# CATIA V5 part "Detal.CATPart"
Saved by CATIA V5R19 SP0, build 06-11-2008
Part number: Detal
Bounding box of the stored display mesh (mm): x -52.829 to 97.171, y -21.934 to 128.066, z 0 to 80
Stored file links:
  E:\Podręcznik\catia\symulacja\Z modelem obrabiarki\Detal\Detal.CATPart
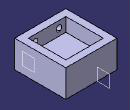
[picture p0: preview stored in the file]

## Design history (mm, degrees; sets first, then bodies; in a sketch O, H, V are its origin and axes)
Body1 "Detal" (main body)
  Sketch1 on xy-plane, origin (0, 0, 0), H (1, 0, 0), V (0, 1, 0)
    line L1 (-52.8293, 128.0659) -> (97.1707, 128.0659)
    line L2 (97.1707, 128.0659) -> (97.1707, -21.9341)
    line L3 (97.1707, -21.9341) -> (-52.8293, -21.9341)
    line L4 (-52.8293, -21.9341) -> (-52.8293, 128.0659)
    point P3 (97.1707, -21.9341)
    distance P3 L1 = 150
    length L3 = 150
    horizontal: L1 H, L3 H
    vertical: L2 V, L4 V
  Pad1: profile Sketch1, direction (0, 0, 1), length 80
  Sketch2 on end face of Pad1, origin (0, 0, 80), H (1, 0, 0), V (0, 1, 0)
    line L1 (-32.8293, 108.0659) -> (77.1707, 108.0659)
    line L2 (77.1707, 108.0659) -> (77.1707, -1.9341)
    line L3 (77.1707, -1.9341) -> (-32.8293, -1.9341)
    line L4 (-32.8293, -1.9341) -> (-32.8293, 108.0659)
    reference projected line E1 (97.1707, 128.0659) -> (-52.8293, 128.0659) from edge [face of Pad1 from Sketch1.L1 | end face of Pad1]
    reference projected line E2 (97.1707, -21.9341) -> (97.1707, 128.0659) from edge [face of Pad1 from Sketch1.L2 | end face of Pad1]
    reference projected line E3 (-52.8293, -21.9341) -> (97.1707, -21.9341) from edge [face of Pad1 from Sketch1.L3 | end face of Pad1]
    length L1 = 110
    distance L2 E2 = 20
    distance L3 E3 = 20
    length L2 = 110
    horizontal: L1 H, L3 H, E1 H
    vertical: L2 V, L4 V
  Pocket1: profile Sketch2, direction (0, 0, -1), length 40
  Plane1: type Offset, Offset 40, RefPlane face of Pad1 from Sketch1.L2
  Sketch3 on Plane1, origin (57.1707, 0, 0), H (0, -1, 0), V (0, 0, 1)
    axis line L1 (-59.4952, 83.3318) -> (64.7362, 37.931)
    line L2 (-52.1356, 89.1597) -> (64.7008, 46.4614)
    line L3 (64.7008, 46.4614) -> (61.9548, 38.9475)
    point P5 (61.9548, 38.9475)
    line L4 (-52.1356, 89.1597) -> (-54.8816, 81.6458)
    point P6 (-54.8816, 81.6458)
    distance L1 L2 = 8
    perpendicularity: L3 L1, L4 L1
    coincidence: P5 L1, P6 L1
  Groove1: profile Sketch3, axis Sketch3.L1, angle 360
  Plane2: type Offset, Offset 40, RefPlane face of Pad1 from Sketch1.L4
  Sketch4 on Plane2, origin (-12.8293, 0, 0), H (0, 1, 0), V (0, 0, 1)
    axis line L1 (-75.2929, 31.0546) -> (52.1237, 81.2631)
    line L2 (-45.5258, 51.3831) -> (28.5005, 80.5531)
    line L3 (28.5005, 80.5531) -> (31.4334, 73.1101)
    point P1 (31.4334, 73.1101)
    line L4 (-45.5258, 51.3831) -> (-42.5929, 43.9401)
    point P2 (-42.5929, 43.9401)
    distance L1 L2 = 8
    perpendicularity: L3 L1, L4 L1
    coincidence: P1 L1, P2 L1
  Groove2: profile Sketch4, axis Sketch4.L1, angle 360
Body2 "Polfabrykat"
  Sketch5 on start face of Pad1, origin (0, 0, 0), H (1, 0, 0), V (0, -1, 0)
    point P1 (-52.8293, 21.9341)
    line L1 (-52.8293, 21.9341) -> (97.1707, 21.9341)
    line L2 (97.1707, 21.9341) -> (97.1707, -128.0659)
    line L3 (97.1707, -128.0659) -> (-52.8293, -128.0659)
    line L4 (-52.8293, -128.0659) -> (-52.8293, 21.9341)
    point P2 (97.1707, 21.9341)
    point P3 (97.1707, -128.0659)
    reference projected line E1 (-52.8293, 21.9341) -> (97.1707, 21.9341) from edge [start face of Pad1 | face of Pad1 from Sketch1.L3]
    reference projected line E2 (-52.8293, -128.0659) -> (-52.8293, 21.9341) from edge [start face of Pad1 | face of Pad1 from Sketch1.L4]
    distance P1 P2 = 150
    distance P2 P3 = 150
    horizontal: L1 H, L3 H
    vertical: L2 V, L4 V
    perpendicularity: L1 L2
    coincidence: L1 E1, L4 E2
  Pad2: profile Sketch5, direction (0, 0, 1), length 80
